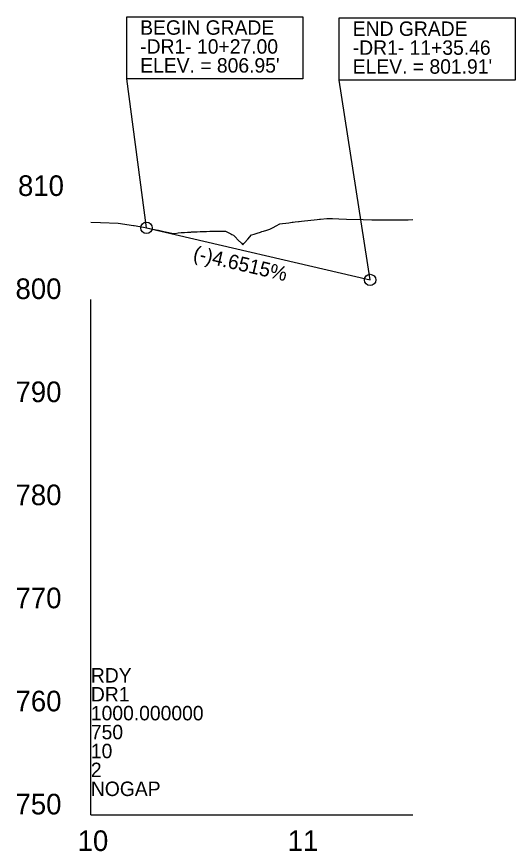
# Model space of a CAD drawing. Extents: x 579185 to 595036, y -53221 to -44640.
# Drawn here: x 592873.7 to 593115.6, y -49552.8 to -49147.9 of the extents above; entities that cross this region are included whole.
import ezdxf

# ---------------------------------------------------------------- set-up
doc = ezdxf.new("R2010")
doc.units = 0
for name, color, linetype in [('Exist Profile Cell', 7, 'Continuous'), ('Exist Vertical Profile Ground Line', 7, 'Continuous'), ('Exist Vertical Profile Horizontal Axis Label Major', 7, 'Continuous'), ('Exist Vertical Profile Vertical Axis Label', 7, 'Continuous'), ('Prop Grid Mask', 7, 'Continuous'), ('Prop Vertical Profile Curve Label', 7, 'Continuous'), ('Prop Vertical Profile Grade', 7, 'Continuous'), ('Prop Vertical Profile Grade Label', 7, 'Continuous'), ('Prop VPI Label', 7, 'Continuous')]:
    doc.layers.add(name, color=color, linetype=linetype)

msp = doc.modelspace()

# ---------------------------------------------------------------- linework, layer by layer
at = {"layer": 'Exist Profile Cell'}
for q in [(592909.73, -49285.12), (593065.94, -49535.12), (592909.73, -49535.12)]:
    msp.add_line((592909.73, -49535.12), q, dxfattribs=at)
at = {"layer": 'Exist Vertical Profile Ground Line'}
msp.add_lwpolyline([(592909.73, -49247.65), (592914.41, -49247.7), (592922.91, -49248.13), (592930.44, -49249.14), (592930.76, -49249.18), (592935.25, -49250.06), (592936.73, -49250.35), (592938.26, -49250.65), (592939.8, -49250.95), (592941.33, -49251.25), (592942.53, -49251.48), (592943.23, -49251.62), (592944.4, -49251.87), (592945.93, -49252.2), (592947.47, -49252.53), (592949, -49252.86), (592950.17, -49253.12), (592950.54, -49253.05), (592952.07, -49252.8), (592953.6, -49252.67), (592954.15, -49252.62), (592955.14, -49252.56), (592956.67, -49252.46), (592958.21, -49252.36), (592958.55, -49252.34), (592959.74, -49252.29), (592961.28, -49252.22), (592962.81, -49252.15), (592964.34, -49252.08), (592964.66, -49252.07), (592965.88, -49252.03), (592967.41, -49251.98), (592968.95, -49251.93), (592970.48, -49251.88), (592970.84, -49251.87), (592972.01, -49251.88), (592973.55, -49251.89), (592975.08, -49251.91), (592976.62, -49252.72), (592977.64, -49253.26), (592978.15, -49253.51), (592978.84, -49253.84), (592979.68, -49254.7), (592981.22, -49256.26), (592982.75, -49257.81), (592983.44, -49258.55), (592983.95, -49257.95), (592984.29, -49257.56), (592985.82, -49255.8), (592987.63, -49253.73), (592988.89, -49253.34), (592990.42, -49252.87), (592991.96, -49252.41), (592992.73, -49252.17), (592993.49, -49251.93), (592995.03, -49251.43), (592996.56, -49250.92), (592997.23, -49250.68), (592998.09, -49250.22), (592999.63, -49249.41), (593001.42, -49248.46), (593002.7, -49248.28), (593004.23, -49248.07), (593005.76, -49247.86), (593007.3, -49247.65), (593007.82, -49247.58), (593008.83, -49247.45), (593010.37, -49247.26), (593010.73, -49247.22), (593011.9, -49247.07), (593013.44, -49246.88), (593014.97, -49246.74), (593016.5, -49246.59), (593018.04, -49246.45), (593019.57, -49246.3), (593020.69, -49246.2), (593021.11, -49246.15), (593024.15, -49245.79), (593026.96, -49245.79), (593030.06, -49245.9), (593033.67, -49246.08), (593041.81, -49246.31), (593046.1, -49246.46), (593052.76, -49246.42), (593063.71, -49246.43), (593065.94, -49246.29)], dxfattribs=at)
at = {"layer": 'Prop Grid Mask'}
for points in [[(592927.1, -49147.91), (593012.5, -49147.91), (593012.5, -49178.1), (592927.1, -49178.1)], [(593030.23, -49148.46), (593115.62, -49148.46), (593115.62, -49178.65), (593030.23, -49178.65)]]:
    msp.add_lwpolyline(points, close=True, dxfattribs=at)
at = {"layer": 'Prop Vertical Profile Curve Label'}
for p, q in [((592936.73, -49250.35), (592927.1, -49178.1)), ((593045.19, -49275.58), (593030.23, -49178.65))]:
    msp.add_line(p, q, dxfattribs=at)
at = {"layer": 'Prop Vertical Profile Grade'}
msp.add_line((592936.73, -49250.35), (593045.19, -49275.58), dxfattribs=at)
at = {"layer": 'Prop VPI Label'}
for centre in [(592936.73, -49250.35), (593045.19, -49275.58)]:
    msp.add_circle(centre, 2.75, dxfattribs=at)

# ---------------------------------------------------------------- texts
at = {"layer": 'Exist Profile Cell'}
for s, p in [('RDY', (592909.73, -49470.88)), ('DR1', (592909.73, -49480.06)), ('1000.000000', (592909.73, -49489.23)), ('750', (592909.73, -49498.41)), ('10', (592909.73, -49507.59)), ('2', (592909.73, -49516.76)), ('NOGAP', (592909.73, -49525.94))]:
    msp.add_text(s, height=7, dxfattribs=at).set_placement(p)
at = {"layer": 'Exist Vertical Profile Horizontal Axis Label Major'}
for s, p in [('10', (592903.31, -49552.62)), ('11', (593005.15, -49552.62))]:
    msp.add_text(s, height=10, dxfattribs=at).set_placement(p)
at = {"layer": 'Exist Vertical Profile Vertical Axis Label'}
for s, p in [('810', (592874.36, -49234.87)), ('800', (592873.16, -49284.87)), ('790', (592873.16, -49334.87)), ('780', (592873.16, -49384.87)), ('770', (592873.16, -49434.87)), ('760', (592873.16, -49484.87)), ('750', (592873.16, -49534.87))]:
    msp.add_text(s, height=10, dxfattribs=at).set_placement(p)
at = {"layer": 'Prop Vertical Profile Grade Label'}
msp.add_text('(-)4.6515%', height=7, rotation=346.9072, dxfattribs=at).set_placement((592958.95, -49265.78))
at = {"layer": 'Prop VPI Label'}
for s, p in [('BEGIN GRADE', (592933.66, -49156.67)), ('END GRADE', (593036.78, -49157.22)), ('-DR1- 10+27.00', (592933.66, -49165.85)), ('-DR1- 11+35.46', (593036.78, -49166.4)), ("ELEV. = 806.95'", (592933.66, -49175.02)), ("ELEV. = 801.91'", (593036.78, -49175.57))]:
    msp.add_text(s, height=7, dxfattribs=at).set_placement(p)

doc.saveas('drawing.dxf')
